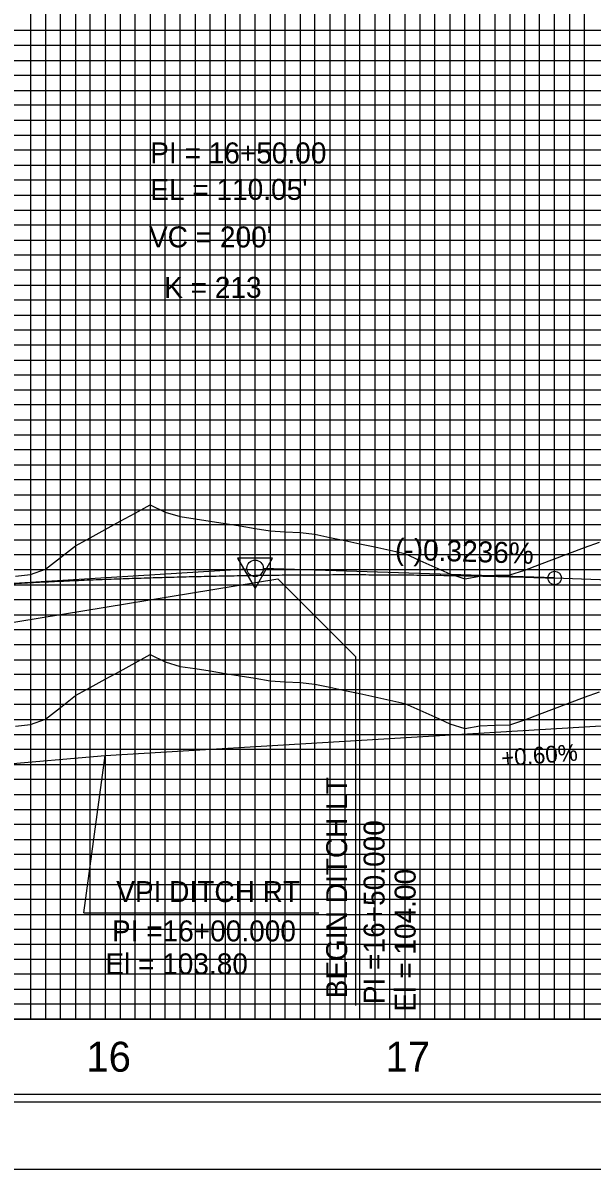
# Model space of a CAD drawing. Extents: x 2345490 to 2436403, y 465165 to 573888.
# Drawn here: x 2412467.8 to 2412657.8, y 527722 to 528104.5 of the extents above; entities that cross this region are included whole.
import ezdxf

# ---------------------------------------------------------------- set-up
doc = ezdxf.new("R2010")
doc.units = 0
for name, color, linetype in [('Old_Level_1', 7, 'Continuous'), ('Old_Level_18', 7, 'Continuous'), ('Old_Level_2', 7, 'Continuous'), ('Old_Level_3', 7, 'Continuous'), ('Old_Level_41', 7, 'Continuous'), ('Old_Level_42', 7, 'Continuous'), ('Old_Level_43', 7, 'Continuous'), ('Old_Level_50', 7, 'Continuous'), ('Old_Level_51', 7, 'Continuous'), ('Old_Level_61', 7, 'Continuous'), ('Old_Level_62', 7, 'Continuous'), ('Old_Level_63', 7, 'Continuous')]:
    doc.layers.add(name, color=color, linetype=linetype)

msp = doc.modelspace()

# ---------------------------------------------------------------- linework, layer by layer
at = {"layer": 'Old_Level_1'}
msp.add_lwpolyline([(2412465.325, 527869.9055), (2412470.325, 527870.41375), (2412475.325, 527872.20025), (2412480.325, 527876.11675), (2412485.325, 527880.03575), (2412490.325, 527882.75425), (2412495.325, 527885.486), (2412500.325, 527888.23125), (2412505.325, 527890.9905), (2412510.325, 527893.76425), (2412515.325, 527891.28875), (2412520.325, 527889.8135), (2412525.325, 527889.049), (2412530.325, 527888.2695), (2412535.325, 527887.4745), (2412540.325, 527886.66375), (2412545.325, 527885.837), (2412550.325, 527884.9935), (2412555.325, 527884.697), (2412560.325, 527884.4625), (2412565.325, 527883.886), (2412570.325, 527882.842), (2412575.325, 527881.78725), (2412580.325, 527880.722), (2412585.325, 527879.646), (2412590.325, 527878.5595), (2412595.325, 527877.46225), (2412600.325, 527875.188), (2412605.325, 527872.91625), (2412610.325, 527870.67475), (2412615.325, 527869.04675), (2412620.325, 527869.919), (2412625.325, 527870.228), (2412630.325, 527870.322), (2412635.325, 527871.95225), (2412640.325, 527873.8325), (2412645.325, 527875.7195), (2412650.325, 527877.61), (2412655.325, 527879.4805), (2412660.325, 527881.29175)], dxfattribs=at)
at = {"layer": 'Old_Level_18'}
msp.add_lwpolyline([(2413745.325, 528797.04275), (2412245.325, 528797.04275), (2412245.325, 527747.04275), (2413745.325, 527747.04275)], close=True, dxfattribs=at)
at = {"layer": 'Old_Level_2'}
for p, q in [((2412445.325, 527916.3765), (2412542.58025, 527922.37375)), ((2412645.325, 527919.30675), (2412548.07375, 527922.45425)), ((2412645.325, 527919.30675), (2412740.325, 527916.23225))]:
    msp.add_line(p, q, dxfattribs=at)
msp.add_lwpolyline([(2412551.19225, 527925.9255), (2412539.44975, 527925.911), (2412545.33325, 527915.79275)], close=True, dxfattribs=at)
for centre, radius in [((2412545.325, 527922.543), 2.75), ((2412645.325, 527919.30675), 2.25)]:
    msp.add_circle(centre, radius, dxfattribs=at)
msp.add_spline([(2412445.325, 527916.3765), (2412449.325, 527916.61925), (2412453.325, 527916.85475), (2412457.325, 527917.0825), (2412461.325, 527917.303), (2412465.325, 527917.51575), (2412469.325, 527917.721), (2412473.325, 527917.91875), (2412477.325, 527918.109), (2412481.325, 527918.29175), (2412485.325, 527918.467), (2412489.325, 527918.63475), (2412493.325, 527918.79475), (2412497.325, 527918.9475), (2412501.325, 527919.0925), (2412505.325, 527919.23025), (2412509.325, 527919.36025), (2412513.325, 527919.48275), (2412517.325, 527919.59775), (2412521.325, 527919.70525), (2412525.325, 527919.80525), (2412529.325, 527919.89775), (2412533.325, 527919.98275), (2412537.325, 527920.06), (2412541.325, 527920.13), (2412545.325, 527920.19225), (2412549.325, 527920.24725), (2412553.325, 527920.2945), (2412557.325, 527920.33425), (2412561.325, 527920.3665), (2412565.325, 527920.39125), (2412569.325, 527920.4085), (2412573.325, 527920.41825), (2412577.325, 527920.4205), (2412581.325, 527920.41525), (2412585.325, 527920.40225), (2412589.325, 527920.382), (2412593.325, 527920.354), (2412597.325, 527920.3185), (2412601.325, 527920.27575), (2412605.325, 527920.22525), (2412609.325, 527920.16725), (2412613.325, 527920.10175), (2412617.325, 527920.02875), (2412621.325, 527919.948), (2412625.325, 527919.86), (2412629.325, 527919.7645), (2412633.325, 527919.66125), (2412637.325, 527919.55075), (2412641.325, 527919.4325), (2412645.325, 527919.30675)], degree=3, dxfattribs=at)
at = {"layer": 'Old_Level_3'}
for p, q in [((2412308.63157, 527879.04516), (2412552.93924, 527919.02289)), ((2412552.93924, 527919.02289), (2412578.85504, 527893.10709)), ((2412578.85504, 527893.10709), (2412578.85504, 527776.66709)), ((2412495.325, 527860.04275), (2412745.325, 527875.04275)), ((2412380.325, 527850.24275), (2412495.325, 527860.04275)), ((2412488.20072, 527807.56895), (2412495.325, 527860.04275)), ((2412488.20072, 527807.56895), (2412566.62021, 527807.56895))]:
    msp.add_line(p, q, dxfattribs=at)
at = {"layer": 'Old_Level_41'}
msp.add_line((2413745.325, 527772.04275), (2412245.325, 527772.04275), dxfattribs=at)
for points in [[(2412470.325, 528797.04275), (2412470.325, 527772.04275), (2412520.325, 527772.04275), (2412520.325, 528797.04275)], [(2412495.325, 528797.04275), (2412495.325, 527772.04275), (2412545.325, 527772.04275), (2412545.325, 528797.04275)], [(2412570.325, 528797.04275), (2412570.325, 527772.04275), (2412620.325, 527772.04275), (2412620.325, 528797.04275)], [(2412595.325, 528797.04275), (2412595.325, 527772.04275), (2412645.325, 527772.04275), (2412645.325, 528797.04275)], [(2413745.325, 528097.04275), (2412245.325, 528097.04275), (2412245.325, 528047.04275), (2413745.325, 528047.04275)], [(2413745.325, 528022.04275), (2412245.325, 528022.04275), (2412245.325, 528072.04275), (2413745.325, 528072.04275)], [(2413745.325, 527997.04275), (2412245.325, 527997.04275), (2412245.325, 527947.04275), (2413745.325, 527947.04275)], [(2413745.325, 527897.04275), (2412245.325, 527897.04275), (2412245.325, 527847.04275), (2413745.325, 527847.04275)], [(2413745.325, 527822.04275), (2412245.325, 527822.04275), (2412245.325, 527872.04275), (2413745.325, 527872.04275)], [(2413745.325, 527797.04275), (2412245.325, 527797.04275)]]:
    msp.add_lwpolyline(points, dxfattribs=at)
at = {"layer": 'Old_Level_42'}
msp.add_lwpolyline([(2413745.325, 527922.04275), (2412245.325, 527922.04275), (2412245.325, 527972.04275), (2413745.325, 527972.04275)], dxfattribs=at)
at = {"layer": 'Old_Level_43'}
for points in [[(2412475.325, 528797.04275), (2412475.325, 527772.04275), (2412480.325, 527772.04275), (2412480.325, 528797.04275)], [(2412485.325, 528797.04275), (2412485.325, 527772.04275), (2412490.325, 527772.04275), (2412490.325, 528797.04275)], [(2412500.325, 528797.04275), (2412500.325, 527772.04275), (2412505.325, 527772.04275), (2412505.325, 528797.04275)], [(2412510.325, 528797.04275), (2412510.325, 527772.04275), (2412515.325, 527772.04275), (2412515.325, 528797.04275)], [(2412525.325, 528797.04275), (2412525.325, 527772.04275), (2412530.325, 527772.04275), (2412530.325, 528797.04275)], [(2412535.325, 528797.04275), (2412535.325, 527772.04275), (2412540.325, 527772.04275), (2412540.325, 528797.04275)], [(2412550.325, 528797.04275), (2412550.325, 527772.04275), (2412555.325, 527772.04275), (2412555.325, 528797.04275)], [(2412560.325, 528797.04275), (2412560.325, 527772.04275), (2412565.325, 527772.04275), (2412565.325, 528797.04275)], [(2412575.325, 528797.04275), (2412575.325, 527772.04275), (2412580.325, 527772.04275), (2412580.325, 528797.04275)], [(2412585.325, 528797.04275), (2412585.325, 527772.04275), (2412590.325, 527772.04275), (2412590.325, 528797.04275)], [(2412600.325, 528797.04275), (2412600.325, 527772.04275), (2412605.325, 527772.04275), (2412605.325, 528797.04275)], [(2412610.325, 528797.04275), (2412610.325, 527772.04275), (2412615.325, 527772.04275), (2412615.325, 528797.04275)], [(2412625.325, 528797.04275), (2412625.325, 527772.04275), (2412640.325, 527772.04275), (2412640.325, 528797.04275)], [(2412630.325, 528797.04275), (2412630.325, 527772.04275), (2412635.325, 527772.04275), (2412635.325, 528797.04275)], [(2412630.325, 528796.44275), (2412630.325, 527772.04275), (2412635.325, 527772.04275), (2412635.325, 528796.44275)], [(2412650.325, 528797.04275), (2412650.325, 527772.04275), (2412655.325, 527772.04275), (2412655.325, 528797.04275)], [(2413695.325, 528102.04275), (2412295.325, 528102.04275), (2412295.325, 528092.04275), (2413695.325, 528092.04275)], [(2413695.325, 528087.04275), (2412295.325, 528087.04275), (2412295.325, 528082.04275), (2413695.325, 528082.04275)], [(2413695.325, 528077.04275), (2412295.325, 528077.04275), (2412295.325, 528067.04275), (2413695.325, 528067.04275)], [(2413695.325, 528062.04275), (2412295.325, 528062.04275), (2412295.325, 528057.04275), (2413695.325, 528057.04275)], [(2413695.325, 528052.04275), (2412295.325, 528052.04275), (2412295.325, 528042.04275), (2413695.325, 528042.04275)], [(2413695.325, 528037.04275), (2412295.325, 528037.04275), (2412295.325, 528032.04275), (2413695.325, 528032.04275)], [(2413695.325, 528027.04275), (2412295.325, 528027.04275), (2412295.325, 528017.04275), (2413695.325, 528017.04275)], [(2413695.325, 528012.04275), (2412295.325, 528012.04275), (2412295.325, 528007.04275), (2413695.325, 528007.04275)], [(2413695.325, 528002.04275), (2412295.325, 528002.04275), (2412295.325, 527992.04275), (2413695.325, 527992.04275)], [(2413695.325, 527987.04275), (2412295.325, 527987.04275), (2412295.325, 527982.04275), (2413695.325, 527982.04275)], [(2413695.325, 527977.04275), (2412295.325, 527977.04275)], [(2412295.325, 527967.04275), (2413695.325, 527967.04275)], [(2413695.325, 527962.04275), (2412295.325, 527962.04275), (2412295.325, 527957.04275), (2413695.325, 527957.04275)], [(2413695.325, 527952.04275), (2412295.325, 527952.04275)], [(2412295.325, 527942.04275), (2413695.325, 527942.04275)], [(2413695.325, 527937.04275), (2412295.325, 527937.04275), (2412295.325, 527932.04275), (2413695.325, 527932.04275)], [(2413695.325, 527927.04275), (2412295.325, 527927.04275), (2412295.325, 527917.04275), (2413695.325, 527917.04275)], [(2413695.325, 527912.04275), (2412295.325, 527912.04275), (2412295.325, 527907.04275), (2413695.325, 527907.04275)], [(2413695.325, 527902.04275), (2412295.325, 527902.04275), (2412295.325, 527892.04275), (2413695.325, 527892.04275)], [(2413695.325, 527887.04275), (2412295.325, 527887.04275), (2412295.325, 527882.04275), (2413695.325, 527882.04275)], [(2413695.325, 527877.04275), (2412295.325, 527877.04275), (2412295.325, 527867.04275), (2413695.325, 527867.04275)], [(2413695.325, 527862.04275), (2412295.325, 527862.04275), (2412295.325, 527857.04275), (2413695.325, 527857.04275)], [(2413695.325, 527852.04275), (2412295.325, 527852.04275), (2412295.325, 527842.04275), (2413695.325, 527842.04275)], [(2413695.325, 527837.04275), (2412295.325, 527837.04275), (2412295.325, 527832.04275), (2413695.325, 527832.04275)], [(2413695.325, 527827.04275), (2412295.325, 527827.04275), (2412295.325, 527817.04275), (2413695.325, 527817.04275)], [(2413695.325, 527812.04275), (2412295.325, 527812.04275), (2412295.325, 527807.04275), (2413695.325, 527807.04275)], [(2413695.325, 527802.04275), (2412295.325, 527802.04275), (2412295.325, 527792.04275), (2413695.325, 527792.04275)], [(2413695.325, 527787.04275), (2412295.325, 527787.04275), (2412295.325, 527782.04275), (2413695.325, 527782.04275)], [(2413695.325, 527777.04275), (2412295.325, 527777.04275)]]:
    msp.add_lwpolyline(points, dxfattribs=at)
at = {"layer": 'Old_Level_50'}
msp.add_lwpolyline([(2413757.825, 528799.59275), (2412091.325, 528799.59275), (2412091.325, 527744.49275), (2413757.825, 527744.49275)], close=True, dxfattribs=at)
at = {"layer": 'Old_Level_51'}
msp.add_lwpolyline([(2413762.325, 528822.04275), (2412078.325, 528822.04275), (2412078.325, 527722.04275), (2413762.325, 527722.04275)], close=True, dxfattribs=at)
at = {"layer": 'Old_Level_61'}
msp.add_lwpolyline([(2412465.325, 527919.9055), (2412470.325, 527920.41375), (2412475.325, 527922.20025), (2412480.325, 527926.11675), (2412485.325, 527930.03575), (2412490.325, 527932.75425), (2412495.325, 527935.486), (2412500.325, 527938.23125), (2412505.325, 527940.9905), (2412510.325, 527943.76425), (2412515.325, 527941.28875), (2412520.325, 527939.8135), (2412525.325, 527939.049), (2412530.325, 527938.2695), (2412535.325, 527937.4745), (2412540.325, 527936.66375), (2412545.325, 527935.837), (2412550.325, 527934.9935), (2412555.325, 527934.697), (2412560.325, 527934.4625), (2412565.325, 527933.886), (2412570.325, 527932.842), (2412575.325, 527931.78725), (2412580.325, 527930.722), (2412585.325, 527929.646), (2412590.325, 527928.5595), (2412595.325, 527927.46225), (2412600.325, 527925.188), (2412605.325, 527922.91625), (2412610.325, 527920.67475), (2412615.325, 527919.04675), (2412620.325, 527919.919), (2412625.325, 527920.228), (2412630.325, 527920.322), (2412635.325, 527921.95225), (2412640.325, 527923.8325), (2412645.325, 527925.7195), (2412650.325, 527927.61), (2412655.325, 527929.4805), (2412660.325, 527931.29175)], dxfattribs=at)
at = {"layer": 'Old_Level_63'}
msp.add_line((2410895.325, 527772.04275), (2413081.64925, 527772.04275), dxfattribs=at)

# ---------------------------------------------------------------- texts
at = {"layer": 'Old_Level_2'}
for s, height, p in [('PI = 16+50.00', 7.0000005, (2412510.325, 528057.66357)), ("EL = 110.05'", 7.0000005, (2412510.325, 528045.48507)), ("VC = 200'", 7.000001, (2412509.9095, 528029.62482)), ('K = 213', 7.000001, (2412514.96875, 528012.79807))]:
    msp.add_text(s, height=height, dxfattribs=at).set_placement(p)
msp.add_text('(-)0.3236%', height=7.000001, rotation=358.1463472, dxfattribs=at).set_placement((2412591.95404, 527925.4942))
at = {"layer": 'Old_Level_3'}
for s, height, rotation, p in [('+0.60%', 5.6, 4.5017741, (2412627.67698, 527856.37568)), ('BEGIN DITCH LT', 7.0000005, 90, (2412576.05736, 527779.01211)), ('PI =16+50.000', 7.0000005, 90, (2412588.55439, 527777.07196)), ('El = 104.00', 7.0000005, 90, (2412598.92046, 527774.6135)), ('VPI DITCH RT', 7.0000005, 360, (2412498.96842, 527811.13273)), ('PI =16+00.000', 7.0000005, 360, (2412497.54012, 527798.02128)), ('El = 103.80', 7.0000005, 360, (2412495.31442, 527787.029))]:
    msp.add_text(s, height=height, rotation=rotation, dxfattribs=at).set_placement(p)
at = {"layer": 'Old_Level_62'}
for s, p in [('16', (2412489.007, 527754.543)), ('17', (2412588.8645, 527754.543))]:
    msp.add_text(s, height=10.000001, dxfattribs=at).set_placement(p)

doc.saveas('drawing.dxf')
